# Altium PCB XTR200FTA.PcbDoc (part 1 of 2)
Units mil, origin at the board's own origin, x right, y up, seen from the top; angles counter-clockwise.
Board outline 3639.76 x 1623.7 mil, 4 copper layers (Top Layer, Layer 1, Layer 2, Bottom Layer), stack 53.912 mil thick; 93 components, 52 nets, 249 pads, 61 vias.
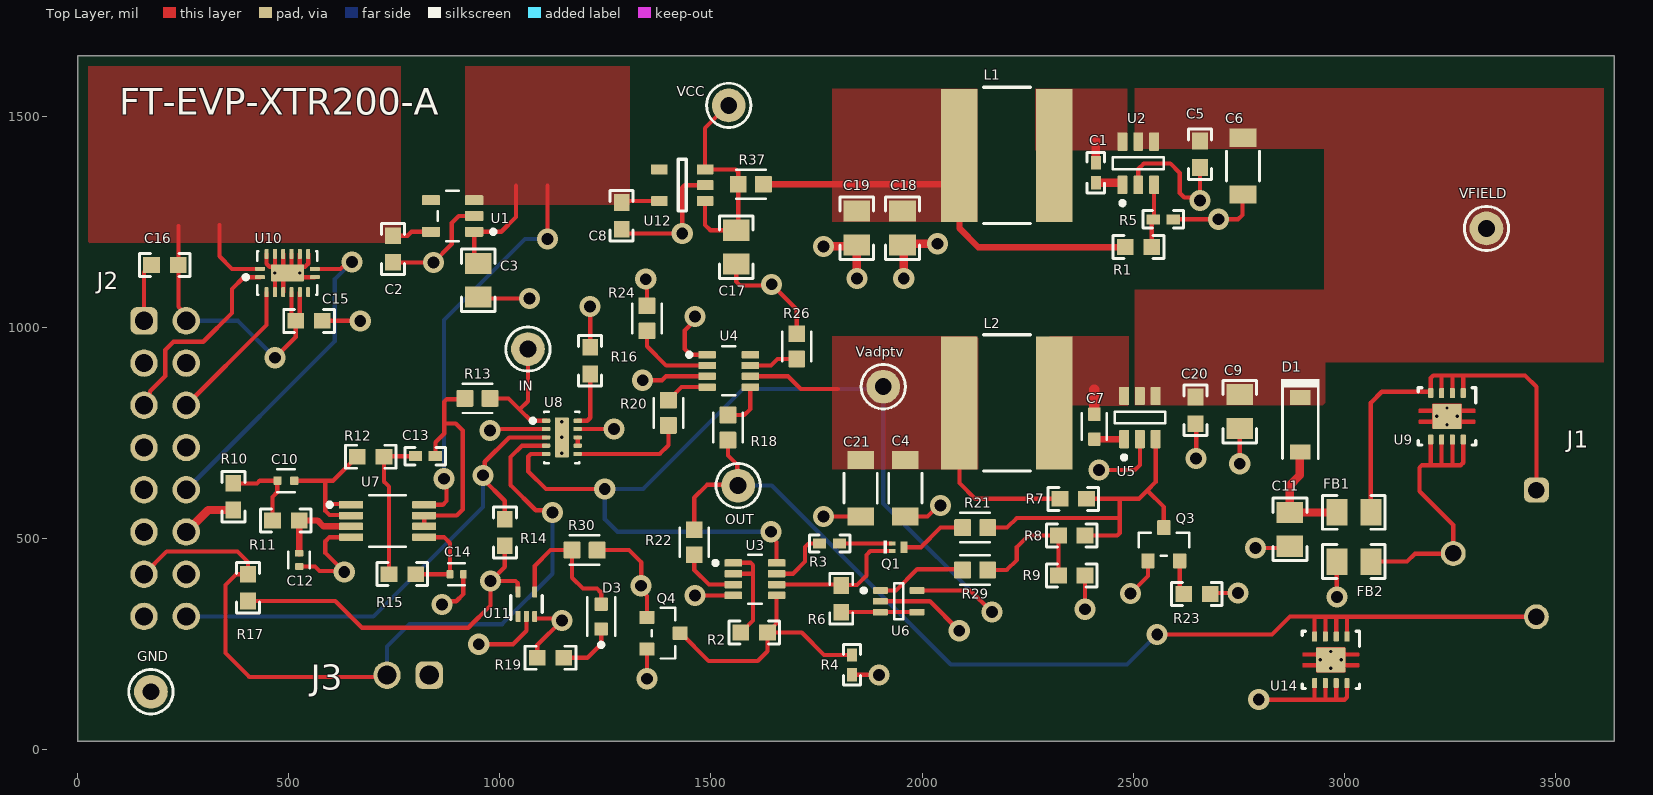
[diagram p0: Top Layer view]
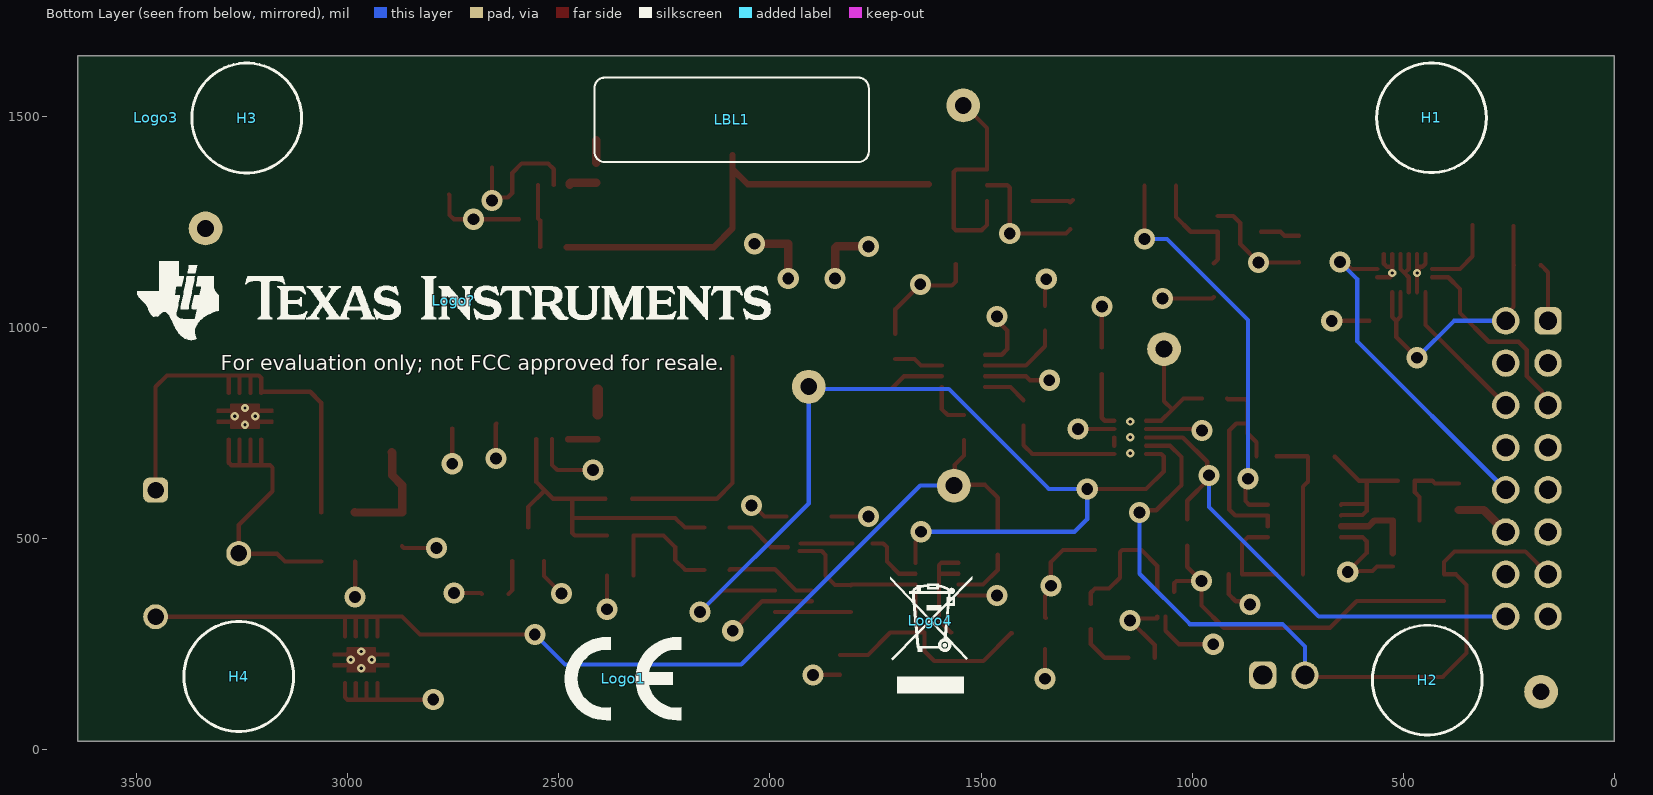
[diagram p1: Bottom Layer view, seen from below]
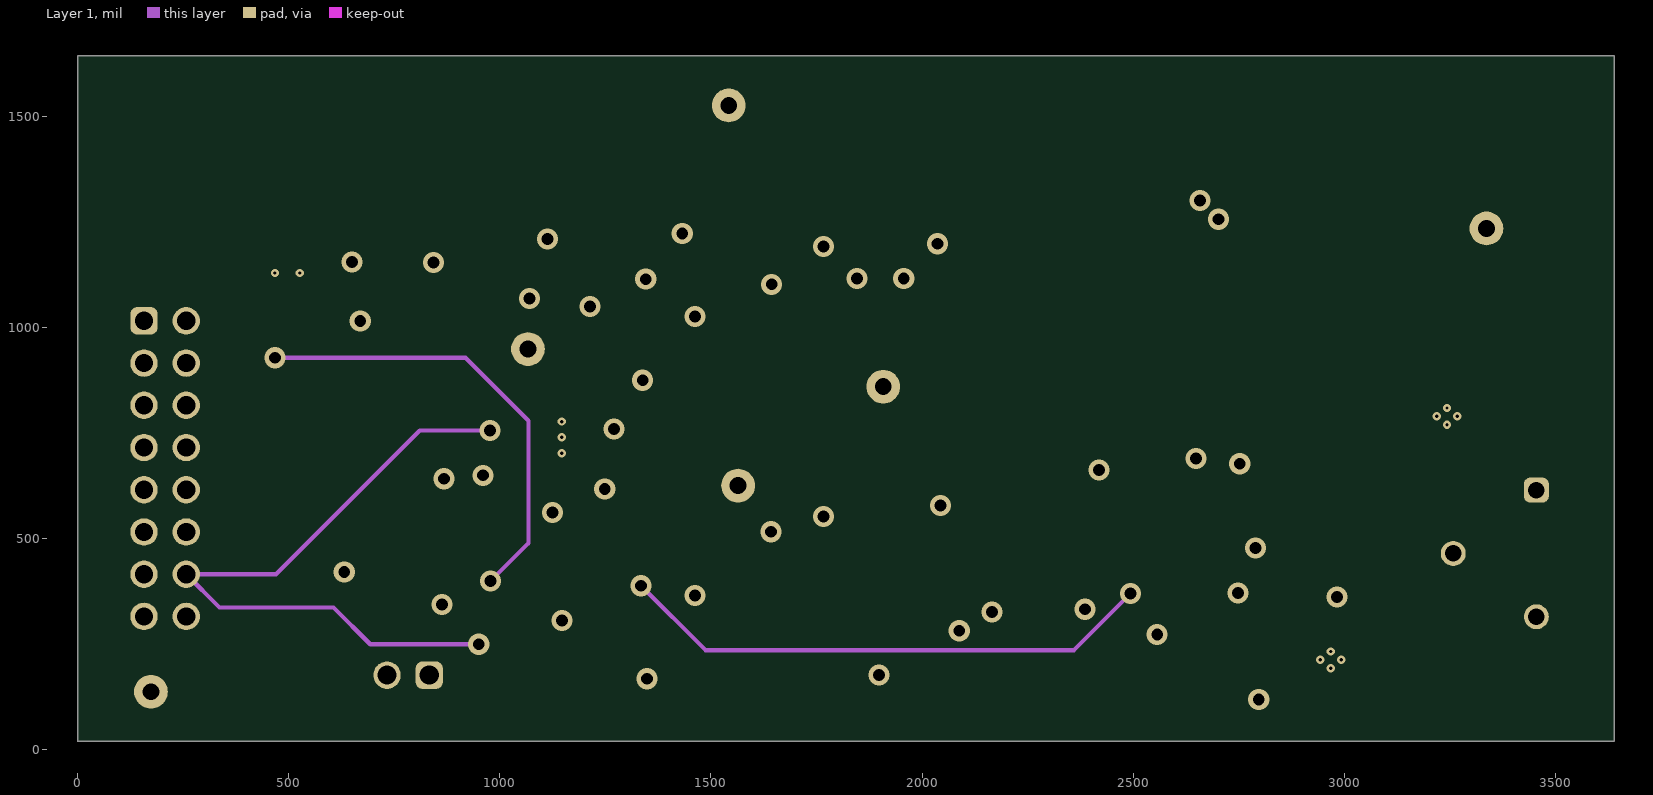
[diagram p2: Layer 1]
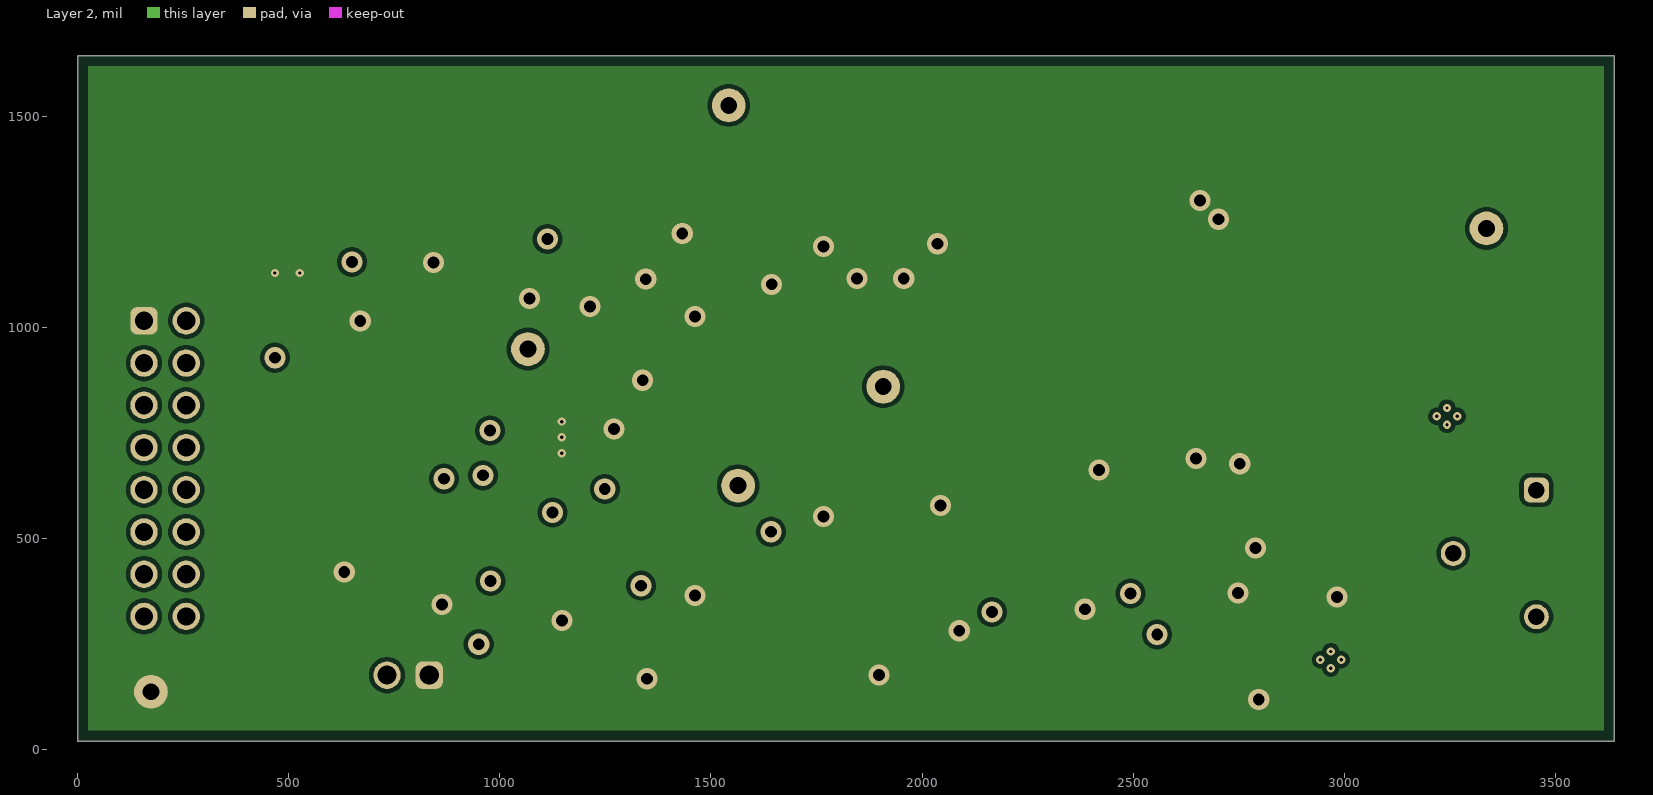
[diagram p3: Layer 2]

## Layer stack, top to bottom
Top Solder: solder mask 1, SM-001, Dk 4
Top Layer: signal copper 1.378
Dielectric 1: prepreg 5.1, PP-017, Dk 4.3
Dielectric 3: prepreg 5.1, PP-017, Dk 4.3
Layer 1: signal copper 1.378
Dielectric1: core 28, Core-039, Dk 4.8
Layer 2: signal copper 1.378
Dielectric 4: prepreg 5.1, PP-017, Dk 4.3
Dielectric 2: prepreg 5.1, PP-017, Dk 4.3
Bottom Layer: signal copper 1.378
Bottom Solder: solder mask 1, SM-001, Dk 4

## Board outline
-0.01,20 3639.75,20 3639.75,1643.7 -0.01,1643.7

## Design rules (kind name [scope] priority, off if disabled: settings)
AcuteAngle [All] p1: minimum=4.50000000000000E+0001 checktracksonly=FALSE
AssemblyTestPointUsage [All] p1: valid=2
BoardOutlineClearance BoardOutlineClearance_MountingHoles [OnCopper and InComponentClass('Mounting Holes')] p1: gap=39.37 ignorepadtopadclearanceinfootprint=FALSE
BoardOutlineClearance BoardOutlineClearance_Poly [OnCopper and IsPoly] p2: gap=25 ignorepadtopadclearanceinfootprint=FALSE
BoardOutlineClearance [OnCopper and Not InComponentClass('Logo') and not InComponentClass('FiducialMark') and not InRegion(1000,500,4000,800) and not InPoly] p3: gap=40 ignorepadtopadclearanceinfootprint=FALSE
Clearance Clearance_Keepouts [((IsTrack Or IsArc) And Not InPoly) And IsFree and IsKeepOut vs ((IsTrack Or IsArc) And Not InPoly) And IsFree and IsKeepOut] p1: gap=3.94 ignorepadtopadclearanceinfootprint=TRUE
Clearance Clearance_Poly [InPolygon] p2: gap=10 ignorepadtopadclearanceinfootprint=TRUE
Clearance Clearance_FiducialMark [IsKeepOut and InComponentClass('FiducialMark') vs IsPad and InComponentClass('FiducialMark')] p3: gap=0 ignorepadtopadclearanceinfootprint=FALSE
Clearance [All] p4: gap=3.94 ignorepadtopadclearanceinfootprint=TRUE
ComponentClearance ComponentClearance_MountingHoles_FiducialMarks [InComponentClass('Mounting Holes') vs InComponentClass('FiducialMark')] p1: gap=50 collisioncheckmode=3 verticalgap=10 showdistances=FALSE
ComponentClearance ComponentClearance_Shunt [InComponentClass('Header') vs InComponentClass('Shunt')] p2: gap=0 collisioncheckmode=3 verticalgap=0 showdistances=FALSE
ComponentClearance ComponentClearance_Logo [InComponentClass('Logo')] p3: gap=30 collisioncheckmode=3 verticalgap=10 showdistances=FALSE
ComponentClearance ComponentClearance_ScrewToNut [(HasFootprint('NY PMS 440 0025 PH')) vs (HasFootprint('Keystone_1902C'))] p4: gap=5 collisioncheckmode=3 verticalgap=10 showdistances=FALSE
ComponentClearance ComponentClearance_MountingHoles [InComponentClass('Mounting Holes')] p5: gap=100 collisioncheckmode=3 verticalgap=100000 showdistances=FALSE
ComponentClearance ComponentClearance_SmallPassives [HasFootprint('0201*') or HasFootprint('0402*') or HasFootprint('0508') or HasFootprint('0603*') or HasFootprint('0612') or HasFootprint('0805*') or HasFootprint('0815*') or HasFootprint('0830*') or HasFootprint('1206*') or HasFootprint('1210*') or HasFootprint('1808*') or HasFootprint('1812*') or HasFootprint('1825*') or HasFootprint('2010*') or HasFootprint('2220*') or HasFootprint('2225*') or HasFootprint('2512*') or HasFootprint('2728*') or HasFootprint('3518*') vs HasFootprint('0201*') or HasFootprint('0402*') or HasFootprint('0508') or HasFootprint('0603*') or HasFootprint('0612') or HasFootprint('0805*') or HasFootprint('0815*') or HasFootprint('0830*') or HasFootprint('1206*') or HasFootprint('1210*') or HasFootprint('1808*') or HasFootprint('1812*') or HasFootprint('1825*') or HasFootprint('2010*') or HasFootprint('2220*') or HasFootprint('2225*') or HasFootprint('2512*') or HasFootprint('2728*') or HasFootprint('3518*')] p6: gap=14.96 collisioncheckmode=3 verticalgap=10 showdistances=FALSE
ComponentClearance ComponentClearance_THtoSMT [IsThruComponent vs IsSMTComponent] p7: gap=30 collisioncheckmode=3 verticalgap=30 showdistances=FALSE
ComponentClearance ComponentClearance_THtoTH [IsThruComponent vs IsThruComponent] p8: gap=20 collisioncheckmode=3 verticalgap=30 showdistances=FALSE
ComponentClearance [All] p9: gap=20 collisioncheckmode=3 verticalgap=10 showdistances=FALSE
DiffPairsRouting [All] p1: maxlimit=100 minlimit=10 mostfreqgap=10 toplayer_minwidth=15 toplayer_maxwidth=15 toplayer_prefwidth=15 midlayer1_minwidth=15 midlayer1_maxwidth=15 midlayer1_prefwidth=15 midlayer2_minwidth=15 midlayer2_maxwidth=15 midlayer2_prefwidth=15 bottomlayer_minwidth=15 bottomlayer_maxwidth=15 bottomlayer_prefwidth=15 maxuncoupledlength=1000
FabricationTestPointUsage TestPointUsage [All] p1: valid=2 allowmultiple=FALSE
FabricationTestpoint Testpoint [All] p1: side=3 testpointundercomponent=TRUE minsize=40 maxsize=100 preferedsize=60 minholesize=0 maxholesize=40 preferedholesize=32 testpointgrid=1 allowsidetop=TRUE allowsidebottom=TRUE usegrid=TRUE gridtolerance=0.01
FanoutControl Fanout_LCC [IsLCC] p1: bgadir=Out bgaviamode=Centered fanoutstyle=Auto fanoutdirection=Alternating viagrid=1 // Fanout_LCC (Default Rule)
FanoutControl Fanout_BGA [IsBGA] p2: bgadir=Out bgaviamode=Centered fanoutstyle=Auto fanoutdirection=Alternating viagrid=1 // Fanout_BGA (Default Rule)
FanoutControl Fanout_Default [All] p4: bgadir=Out bgaviamode=Centered fanoutstyle=Auto fanoutdirection=Alternating viagrid=1 // Fanout_Default (Default Rule)
FanoutControl Fanout_Small [(CompPinCount < 5)] p5: bgadir=Out bgaviamode=Centered fanoutstyle=Auto fanoutdirection=OutThenIn viagrid=1 // Fanout_Small (Default Rule)
HoleSize [All] p1: absolutevalues=TRUE maxlimit=251 minlimit=7.87 maxpercent=80.000 minpercent=20.000
MinimumAnnularRing MinimumAnnularRing_ThermalPadVias [IsVia and InAnyComponent] p1: minimumring=5.91
MinimumAnnularRing [All] p2: minimumring=7.09
MinimumSolderMaskSliver MinimumSolderMaskSliver_Logo [InComponentClass('Logo') vs InComponentClass('Logo')] p1: minsoldermaskwidth=0.7
MinimumSolderMaskSliver [All] p2: minsoldermaskwidth=3.94
PlaneConnect [All] p1: planeconnectstyle=Relief reliefexpansion=10 reliefentries=4 reliefconductorwidth=10 reliefairgap=10
PolygonConnect [All] p1: connectstyle=Direct reliefconductorwidth=10 reliefentries=4 polygonreliefangle="90 Angle" airgapwidth=10
RoutingVias [All] p1: holewidth=16 width=34 viastyle="Through Hole" minholewidth=19.68 minwidth=33.86 maxholewidth=40 maxwidth=65
RoutingVias ThermalPadVias [IsVia and InAnyComponent] p2: holewidth=7.87 width=19.68 viastyle="Through Hole" minholewidth=7.87 minwidth=19.68 maxholewidth=12.99 maxwidth=23.62
SilkToBoardRegionClearance [Not ((IsComment or IsDesignator) And (Hide <> 'False')) and not InRegion(1000,500,4000,800)] p1:
SilkToSilkClearance SilkToSilkClearance_Pb-FreeLogo [(HasFootprint('Pb-Free_Overlay_Medium') OR HasFootprint('Pb-Free_Overlay_Small')) vs (HasFootprint('Pb-Free_Overlay_Medium') OR HasFootprint('Pb-Free_Overlay_Small'))] p1: silktosilkclearance=0
SilkToSilkClearance [All] p2: silktosilkclearance=3.94
SilkToSolderMaskClearance SilkToComponentPadClearance [(IsPad or IsFill or IsRegion) and InAnycomponent] p1: minsilkscreentomaskgap=5 clearancetoexposedcopper=TRUE
SilkToSolderMaskClearance "Silk to Solder Mask Opening" [All] p2: minsilkscreentomaskgap=3.94 clearancetoexposedcopper=FALSE
SolderMaskExpansion TentAllVias [IsVia] p1: expansion=1.97 istentingtop=TRUE
SolderMaskExpansion SolderMaskExpansion_1 [All] p2: expansion=4 istentingtop=FALSE
SupplyNets "Schematic Supply Nets_2" [InNet('LDO_IN')] p1: voltage=0.000
SupplyNets "Schematic Supply Nets_7" [InNet('VDD-5V')] p2: voltage=0.000
SupplyNets "Schematic Supply Nets_6" [InNet('GND')] p3: voltage=0.000
SupplyNets "Schematic Supply Nets_4" [InNet('VDD-3V3')] p4: voltage=0.000
SupplyNets "Schematic Supply Nets_1" [InNet('Vbuck_out')] p5: voltage=0.000
SupplyNets "Schematic Supply Nets" [InNet('Vfield')] p6: voltage=0.000
UnRoutedNet [All] p1: checkbadconnections=TRUE
Width [All] p1: maxlimit=100 minlimit=4 preferedwidth=10 checkconnectedcopper=TRUE
14 further rules are at their usual default settings.

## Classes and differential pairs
component class Schematic: C1 C2 C3 C4 C5 C6 C7 C8 C9 C10 C11 C12 C13 C14 C15 C16 C17 C18 C19 C20 C21 D1 D3 FB1 FB2 GND IN J1 J2 J3 L1 L2 OUT Q1 Q3 Q4 R1 R2 R3 R4 R5 R6 R7 R8 R9 R10 R11 R12 R13 R14 R15 R16 R17 R18 R19 R20 R21 R22 R23 R24 R26 R29 R30 R37 U1 U2 U3 U4 U5 U6 U7 U8 U9 U10 U11 U12 U14 Vadptv Vcc VFIELD
component class Header: J2 J3
component class Logo: Logo?
component class Hardware: H1 H2 H3 H4 LBL1 Logo1 Logo3 Logo4 Logo? ZZ1 ZZ2 ZZ3 ZZ4
component class AssemblyNote: ZZ1 ZZ2 ZZ3 ZZ4
component class Label: LBL1

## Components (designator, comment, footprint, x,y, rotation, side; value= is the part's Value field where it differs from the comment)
C1 "GRM155R71C104KA88D" 0402 2411.61,1366.14 r270 top value=0.1uF
C2 "885012206052" 0603 747.1,1185.48 r90 top value=1uF
C3 "GRM21BR71C225KA12L" 0805_HV 949.1,1111.48 r90 top value=2.2uF
C4 "C3216X6S1V106K160AC" 1206_180 1960.65,619.12 r90 top value=10uF
C5 "GRM188R72A104KA35D" 0603 2658.46,1409.88 r270 top value=0.1uF
C6 "GRM31CR71H475KA12L" 1206_180 2759.96,1381.68 r270 top value=4.7uF
C7 "KGF15AR71H104KT" FP-KGF15AR71H104KT_0603-MFG 2408.2,764.68 r90 top value=100nF
C8 "885012206052" 0603 1288.59,1263.99 r90 top value=1uF
C9 "GRM21BR61H475KE51L" 0805_HV 2752.33,800.53 r270 top value=4.7uF
C10 "CC0402KRX7R7BB123" FP-CC0402KRX7R7BB123_0402-MFG 493.37,636.81 r0 top value=12nF
C11 "CC0805KRX7R9BB102" 0805_HV 2871.06,521.49 r270 top value=1000pF
C12 "GRM155R71H103JA88D" FP-GRM155R71H103JA88D_0402-MFG 524.86,449.35 r90 top value=10nF
C13 "GRM155R71C683KA88D" 0402 823.83,694.88 r180 top value=0.068uF
C14 "GRM155R71H103JA88D" FP-GRM155R71H103JA88D_0402-MFG 897.94,415.35 r180 top value=10nF
C15 "885012206020" 0603 548.35,1015.35 r0 top value=0.1uF
C16 "885012206020" 0603 206.69,1147.25 r180 top value=0.1uF
C17 "GRM21BR71C225KA12L" 0805_HV 1559.78,1189.99 r90 top value=2.2uF
C18 "GRM21BR61A226ME44L" 0805_HV 1953.7,1235.08 r270 top value=22uF
C19 "GRM21BR61A226ME44L" 0805_HV 1845.44,1235.08 r270 top value=22uF
C20 "GRM188R72A104KA35D" 0603 2647.42,803.5 r270 top value=0.1uF
C21 "C3216X6S1V106K160AC" 1206_180 1854.52,619.12 r90 top value=10uF
D1 "SD103AW-7-F" SOD-123 2895.73,769.05 r270 top value=40V
D3 "LTST-C190KFKT" FP-LTST-C190KFKT_0603-MFG 1240.16,314.96 r90 top
FB1 "742792041" 0805_HV 3022.73,561.77 r0 top value="600 ohm"
FB2 "742792041" 0805_HV 3022.73,445.23 r0 top value="600 ohm"
GND "GND" Keystone5002 173.88,137.01 r0 top (schematic designator TP1)
H1 "SJ5382" 3M_SJ5382 433.39,1496.06 r180 bottom
H2 "SJ5382" 3M_SJ5382 443.29,164.64 r180 bottom
H3 "SJ5382" 3M_SJ5382 3239.15,1495.57 r180 bottom
H4 "SJ5382" 3M_SJ5382 3257.87,173.07 r180 bottom
IN "GND" Keystone5002 1066.69,948.43 r90 top (schematic designator TP4)
J1 "691412320003" Wurth_691412320003 3356.3,464.57 r90 top
J2 "61301621021" Wurth_61301621021 207.48,665.35 r0 top
J3 "61300211121" WURTH_61300211121 782.99,176.25 r180 top
L1 "SRN8040-220M" SRN8040 2200.76,1407.48 r0 top value=22uH
L2 "SRN8040-330M" SRN8040 2200.76,821.05 r0 top value=33uH
LBL1 "THT-14-423-10" Label_650x200 2090.83,1491.29 r180 bottom
Logo1 "CE Mark" CE_Mark_5mm 2347.73,167.91 r180 bottom
Logo3 "FCC disclaimer" FCC_disclaimer 3454.72,1496.06 r180 bottom
Logo4 "WEEE logo" WEEE_Minimum 1620.08,305.65 r180 bottom
Logo? "Texas Instruments" TI_Horizontal_Overlay_Medium 2748.23,1062.99 r180 bottom
OUT "GND" Keystone5002 1564.42,625.11 r90 top (schematic designator TP2)
Q1 "MMBT3904LP" DIODES_X1-DFN1006-3 1943.54,479.33 r0 top value="40 V"
Q3 "NTR4003NT3G" FP-NTR4003NT3G_SOT23-3-MFG 2572.57,486.31 r90 top
Q4 "NTR4003NT3G" FP-NTR4003NT3G_SOT23-3-MFG 1387.8,275.59 r0 top
R1 "CRCW0603169KFKEA" 0603 2512.59,1189.99 r180 top value=169k
R2 "CRCW0603261KFKEA" 0603 1602.36,277.11 r0 top value=261k
R3 "ERA-2AEB102X" 0402 1780.92,488.23 r0 top value=1.00k
R4 "RC0402FR-0715KL" 0402 1834.02,200.62 r90 top value=15.0k
R5 "CRCW040222K1FKED" 0402 2570.87,1255.88 r180 top value=22.1k
R6 "RC0603FR-074K87L" 0603 1808.71,357.08 r90 top value=4.87k
R7 "RC0603FR-0790K9L" 0603 2358.02,593.93 r180 top value=90.9k
R8 "RT0603BRD076K49L" 0603 2354.49,506.93 r0 top value=6.49k
R9 "RT0603BRD073K4L" 0603 2354.49,412.26 r180 top value=3.40k
R10 "RC0603FR-076K19L" 0603 369.01,598.96 r90 top value=6.19k
R11 "RT0603DRE078K87L" 0603 493.37,542.72 r0 top value=8.87k
R12 "RT0603DRE072K49L" 0603 694.32,693.49 r180 top value=2.49k
R13 "WSL060300000ZEA9" FP-WSL060300000ZEA9_0603-MFG 947.14,831.75 r180 top value=0
R14 "RG1608P-104-B-T5" 0603 1011.86,514.17 r270 top value=100k
R15 "RT0603DRE073K74L" 0603 769.21,415.35 r0 top value=3.74k
R16 "RT0603BRD071K37L" 0603 1213.99,920.95 r270 top value=1.37k
R17 "RG1608P-104-B-T5" 0603 403.5,383.55 r270 top value=100k
R18 "WSL060300000ZEA9" FP-WSL060300000ZEA9_0603-MFG 1540.17,762.62 r90 top value=0
R19 "RT0603DRE071KL" 0603 1120.08,217.52 r180 top value=1.00k
R20 "WSL060300000ZEA9" FP-WSL060300000ZEA9_0603-MFG 1399.27,797.54 r270 top value=0
R21 "WSL060300000ZEA9" FP-WSL060300000ZEA9_0603-MFG 2125.75,525.68 r0 top value=0
R22 "WSL060300000ZEA9" FP-WSL060300000ZEA9_0603-MFG 1460.63,491.03 r90 top value=0
R23 "RT0603BRD0711K8L" 0603 2650.81,368.66 r180 top value=11.8k
R24 "WSL060300000ZEA9" FP-WSL060300000ZEA9_0603-MFG 1348.43,1021.37 r270 top value=0
R26 "WSL060300000ZEA9" FP-WSL060300000ZEA9_0603-MFG 1703,954.86 r270 top value=0
R29 "WSL060300000ZEA9" FP-WSL060300000ZEA9_0603-MFG 2125.75,425.29 r0 top value=0
R30 "WSL060300000ZEA9" FP-WSL060300000ZEA9_0603-MFG 1200.79,472.44 r180 top value=0
R37 "WSL060300000ZEA9" FP-WSL060300000ZEA9_0603-MFG 1594.49,1338.58 r180 top value=0
U1 "TPS7A0333DBVR" DBV0005A-MFG 888.1,1263.63 r180 top
U2 "LMR54406DBVR" DBV0006A-MFG 2511.93,1388.54 r90 top
U3 "TLV9302IDDFR" DDF0008A-MFG 1604.33,403.54 r0 top
U4 "TPS26611DDFR" DDF0008A-MFG 1542.14,896.79 r0 top
U5 "LMR54406DBVR" DBV0006A-MFG 2515.78,786.41 r90 top
U6 "TLV9301IDCKR" DCK0005A-MFG 1944.45,351.18 r0 top
U7 "OPA2991IDGKR" DGK0008A-MFG 734.31,541.44 r0 top
U8 "XTR200IDQCR" DQC0010A-MFG 1147.07,739.37 r0 top
U9 "TVS3301DRBR" DRB0008A 3243.1,789.29 r270 top
U10 "SN74LV8T165BQBR" BQB0016A-MFG 497,1128.58 r90 top
U11 "SN74LVC1G04DRLR" DRL0005A 1062.99,344.49 r90 top
U12 "TPS70950DBVR" DBV0005A_N 1432.09,1336.61 r180 top
U14 "TVS3301DRBR" DRB0008A 2967.87,212.6 r270 top
Vadptv "GND" Keystone5002 1908.15,859.46 r90 top (schematic designator TP6)
VCC "GND" Keystone5002 1542.14,1525.59 r90 top (schematic designator TP5)
VFIELD "GND" Keystone5002 3336.61,1234.22 r90 top (schematic designator TP3)
ZZ1 "This Assembly Note is for PCB labels only" AssemblyNoteLabel 185,3938 r0 top
ZZ2 "These assemblies are ESD sensitive, ESD precautions shall be observed." AssemblyNote 185,3829.11 r0 top
ZZ3 "These assemblies must be clean and free from flux and all contaminants. Use of no clean flux is not acceptable." AssemblyNote 185,3740.56 r0 top
ZZ4 "These assemblies must comply with workmanship standards IPC-A-610 Class 2, unless otherwise specified." AssemblyNote 185,3652 r0 top

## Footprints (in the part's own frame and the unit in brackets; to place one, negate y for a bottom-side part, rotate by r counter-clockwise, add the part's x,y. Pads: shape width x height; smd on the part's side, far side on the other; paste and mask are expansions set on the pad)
3M_SJ5382 [mil] "3M BUMPON"
  silkscreen extent -130,-130 130,130, body extent -125,-125 125,125, height 75
0402 [mm] "0402 from SM-752 data"
  rect 0.8x0.6 smd: 1(-0.6,0) 2(0.6,0)
  silkscreen extent -1.22,-0.52 1.22,0.52, body extent -0.55,-0.3 0.55,0.3, height 0.6
0603 [mm] "0603 from SM-752 data"
  rect 1x0.95 smd: 1(-0.8,0) 2(0.8,0)
  silkscreen extent -1.52,-0.69 1.52,0.69, body extent -0.87,-0.47 0.87,0.47, height 1
0805_HV [mil] "0805 with 30mil clearance between pads"
  rect 50x63 smd: 1(-40,0) 2(40,0)
  silkscreen extent -74,-40 74,40, body extent -43,-29 43,29, height 57
1206_180 [mm] "1206_180"
  rect 1.1x1.6 smd: 1(-1.7,0) 2(1.7,0)
  silkscreen extent -0.9,-1 0.9,1, body extent -1.75,-0.95 1.75,0.95, height 1.8
AssemblyNote [mil] "Assembly Note"
AssemblyNoteLabel [mil] "Assembly Note for PCB Labels"
BQB0016A-MFG [mm]
  rrect42% 0.24x0.6 smd paste+0 mask+0: 1(-0.25,1.65) 8(-0.25,-1.65) 9(0.25,-1.65) 16(0.25,1.65)
  rrect42% 0.6x0.24 smd paste+0 mask+0: 2(-1.15,1.25) 3(-1.15,0.75) 4(-1.15,0.25) 5(-1.15,-0.25) 6(-1.15,-0.75) 7(-1.15,-1.25) 10(1.15,-1.25) 11(1.15,-0.75) 12(1.15,-0.25) 13(1.15,0.25) 14(1.15,0.75) 15(1.15,1.25)
  rrect10% 1x2 smd paste-1000 mask+0: 17(0,0)
  silkscreen extent -1.3,-1.8 1.3,2.62, body extent -1.55,-2.05 1.55,2.05, height 0.25
CE_Mark_5mm [mil] "Minimum text height for CE Mark"
  silkscreen extent -138,-98 138,98
DBV0005A-MFG [mm]
  rrect17% 1.1x0.6 smd paste+0 mask+0: 1(-1.3,0.95) 2(-1.3,0) 3(-1.3,-0.95) 4(1.3,-0.95) 5(1.3,0.95)
  silkscreen extent -2.58,-1.53 0.87,1.53, body extent -1.95,-1.78 1.95,1.78, height 0.25
DBV0005A_N [mm] "SOT23, 5-Leads, Body 2.9x1.6mm, Pitch 0.95mm, Lead Span 2.8mm, IPC Medium Density"
  rrect17% 1x0.6 smd: 1(-1.375,0.95) 2(-1.375,0) 3(-1.375,-0.95) 4(1.375,-0.95) 5(1.375,0.95)
  silkscreen extent -0.25,-1.55 0.25,1.55, body extent -1.42,-1.46 1.42,1.46, height 1.09
DBV0006A-MFG [mm]
  rrect17% 1.1x0.6 smd paste+0 mask+0: 1(-1.3,0.95) 2(-1.3,0) 3(-1.3,-0.95) 4(1.3,-0.95) 5(1.3,0) 6(1.3,0.95)
  silkscreen extent -2.52,-1.53 0.35,1.53, body extent -1.95,-1.78 1.95,1.78, height 0.25
DCK0005A-MFG [mm]
  rrect25% 0.9x0.4 smd paste-1000 mask+0: 1(-1.1,0.65) 2(-1.1,0) 3(-1.1,-0.65) 4(1.1,-0.65) 5(1.1,0.65)
  silkscreen extent -2.22,-1.07 0.27,1.07, body extent -1.65,-1.33 1.65,1.33, height 0.25
DDF0008A-MFG [mm] "Recommended Land Pattern"
  rrect22% 1.05x0.45 smd paste+0 mask+0: 1(-1.3,0.975) 2(-1.3,0.325) 3(-1.3,-0.325) 4(-1.3,-0.975) 5(1.3,-0.975) 6(1.3,-0.325) 7(1.3,0.325) 8(1.3,0.975)
  silkscreen extent -2.5,-1.48 0.4,1.48, body extent -1.41,-1.45 1.41,1.45, height 1.1
DGK0008A-MFG [mm]
  rrect22% 1.45x0.45 smd paste+0 mask+0: 1(-2.2,0.975) 2(-2.2,0.325) 3(-2.2,-0.325) 4(-2.2,-0.975) 5(2.2,-0.975) 6(2.2,-0.325) 7(2.2,0.325) 8(2.2,0.975)
  silkscreen extent -3.61,-1.55 1.1,1.55, body extent -3.03,-1.8 3.03,1.8, height 0.25
DIODES_X1-DFN1006-3 [mm] "Diodes Recommended"
  rect 0.4x0.25 smd: 1(-0.35,0.225) 2(-0.35,-0.225)
  rect 0.4x0.7 smd: 3(0.35,0)
  silkscreen extent -0.87,-0.38 -0.69,0.38, body extent -0.54,-0.34 0.54,0.34, height 0.53
DQC0010A-MFG [mm] "Recommended Land Pattern"
  rrect40% 0.5x0.25 smd paste+0 mask+0: 1(-0.95,1) 2(-0.95,0.5) 3(-0.95,0) 4(-0.95,-0.5) 5(-0.95,-1) 6(0.95,-1) 7(0.95,-0.5) 8(0.95,0) 9(0.95,0.5) 10(0.95,1)
  rrect12% 0.84x2.4 smd paste-1000 mask+0: 11(0,0)
  silkscreen extent -1.87,-1.55 1.05,1.55, body extent -1.3,-1.65 1.3,1.65, height 0.25
DRB0008A [mm] "VSON-8"
  rrect32% 0.6x0.31 smd: 1(-1.4,0.975) 2(-1.4,0.325) 3(-1.4,-0.325) 4(-1.4,-0.975) 5(1.4,-0.975) 6(1.4,-0.325) 7(1.4,0.325) 8(1.4,0.975)
  rrect7% 1.5x1.75 smd paste-0.75: 9(0,0)
  Top Layer region: -0.7,-0.875 -0.49,-0.875 -0.471,-0.879 -0.455,-0.89 -0.444,-0.906 -0.44,-0.925 -0.44,-0.925 -0.44,-1.65 -0.436,-1.669 -0.425,-1.685 -0.409,-1.696 -0.39,-1.7 -0.39,-1.7 -0.26,-1.7 -0.241,-1.696 -0.225,-1.685 -0.214,-1.669 -0.21,-1.65 -0.21,-1.65 -0.21,-0.925 -0.206,-0.906 -0.195,-0.89 -0.179,-0.879 -0.16,-0.875 -0.16,-0.875 0.16,-0.875 0.179,-0.879 0.195,-0.89 0.206,-0.906 0.21,-0.925 0.21,-0.925 0.21,-1.65 0.21,-1.65 0.214,-1.669 0.225,-1.685 0.241,-1.696 0.26,-1.7 0.26,-1.7 0.39,-1.7 0.409,-1.696 0.425,-1.685 0.436,-1.669 0.44,-1.65 0.44,-1.65 0.44,-0.925 0.444,-0.906 0.455,-0.89 0.471,-0.879 0.49,-0.875 0.49,-0.875 0.7,-0.875 0.719,-0.871 0.735,-0.86 0.746,-0.844 0.75,-0.825 0.75,-0.825 0.75,0.825 0.746,0.844 0.735,0.86 0.719,0.871 0.7,0.875 0.7,0.875 0.49,0.875 0.471,0.879 0.455,0.89 0.444,0.906 0.44,0.925 0.44,0.925 0.44,1.65 0.436,1.669 0.425,1.685 0.409,1.696 0.39,1.7 0.39,1.7 0.26,1.7 0.241,1.696 0.225,1.685 0.214,1.669 0.21,1.65 0.21,1.65 0.21,1.65 0.21,0.925 0.206,0.906 0.195,0.89 0.179,0.879 0.16,0.875 0.16,0.875 -0.16,0.875 -0.179,0.879 -0.195,0.89 -0.206,0.906 -0.21,0.925 -0.21,0.925 -0.21,1.65 -0.214,1.669 -0.225,1.685 -0.241,1.696 -0.26,1.7 -0.26,1.7 -0.39,1.7 -0.409,1.696 -0.425,1.685 -0.436,1.669 -0.44,1.65 -0.44,1.65 -0.44,0.925 -0.444,0.906 -0.455,0.89 -0.471,0.879 -0.49,0.875 -0.49,0.875 -0.7,0.875 -0.719,0.871 -0.735,0.86 -0.746,0.844 -0.75,0.825 -0.75,0.825 -0.75,-0.825 -0.746,-0.844 -0.735,-0.86 -0.719,-0.871 -0.7,-0.875
  silkscreen extent -1.73,-1.73 1.73,1.73, body extent -1.5,-1.5 1.5,1.5, height 0.77
DRL0005A [mm] "SOTFL, 5-Flat Leads, Body 1.2x1.6x0.6mm, Pitch 0.5mm, TI recommended"
  rrect33% 0.67x0.3 smd: 1(-0.74,0.5) 2(-0.74,0) 3(-0.74,-0.5) 4(0.74,-0.5) 5(0.74,0.5)
  silkscreen extent -0.9,-0.95 0.5,0.95, body extent -0.85,-0.85 0.85,0.85, height 0.62
FCC_disclaimer [mil]
FP-CC0402KRX7R7BB123_0402-MFG [mm]
  rrect20% 0.5x0.5 smd paste+0 mask+0: 1(-0.5,0) 2(0.5,0)
  silkscreen extent -0.53,-0.7 0.53,0.7, body extent -0.87,-0.48 0.87,0.48, height 0.25
FP-GRM155R71H103JA88D_0402-MFG [mm]
  rrect25% 0.4x0.5 smd paste+0 mask+0: 1(-0.4,0) 2(0.4,0)
  silkscreen extent -0.5,-0.65 0.5,0.65, body extent -0.7,-0.38 0.7,0.38, height 0.25
FP-KGF15AR71H104KT_0603-MFG [mm]
  rrect13% 0.8x0.75 smd paste+0 mask+0: 1(-0.75,0) 2(0.75,0)
  silkscreen extent -0.8,-0.75 0.8,0.75, body extent -1.25,-0.58 1.25,0.58, height 0.25
FP-LTST-C190KFKT_0603-MFG [mm]
  rrect13% 0.8x0.8 smd paste+0 mask+0: 1(-0.75,0) 2(0.75,0)
  silkscreen extent -1.82,-0.85 1.15,0.85, body extent -1.25,-0.55 1.25,0.55, height 0.25
FP-NTR4003NT3G_SOT23-3-MFG [mm] "Recommended Land Pattern"
  rrect13% 0.9x0.8 smd paste+0 mask+0: 1(-1,0.95) 2(-1,-0.95) 3(1,0)
  silkscreen extent -0.7,-1.52 0.7,1.52, body extent -1.2,-1.45 1.2,1.45, height 1.11
FP-WSL060300000ZEA9_0603-MFG [mm]
  rrect10% 1.01x1.01 smd paste+0 mask+0: 1(-0.755,0) 2(0.755,0)
  silkscreen extent -0.89,-0.88 0.89,0.88, body extent -1.36,-0.61 1.36,0.61, height 0.25
Keystone5002 [mil] "For Keystone 500x miniature loop terminals"
  round 80 hole 40: 1(0,0)
  silkscreen extent -52,-52 52,52, body extent -49,-49 49,49, height 182
Label_650x200 [mil] "Thermal Transfer Label"
  round 1 on Mech14: 0(0,0)
  silkscreen extent -325,-100 325,100, body extent -325,-100 325,100, height 1
SOD-123 [mm] "On Semi recommended land pattern"
  rect 0.915x1.22 smd: 1(-1.637,0) 2(1.637,0)
  silkscreen extent -2.74,-1.17 2.03,1.17, body extent -1.93,-0.9 1.93,0.9, height 1.35
SRN8040 [mm] "SMD, 2-Leads, Body 8x8mm"
  rect 2.2x8 smd: 1(-2.85,0) 2(2.85,0)
  silkscreen extent -1.4,-4.1 1.4,4.1, body extent -4,-4 4,4, height 4
TI_Horizontal_Overlay_Medium [mil]
  silkscreen extent -750,-93 750,94
WEEE_Minimum [mil] "WEEElie bin"
  silkscreen extent -95,-172 99,104
WURTH_61300211121 [mm] "Header, 2.54mm, 2x1, TH"
  rrect50% 1.65x1.65 hole 1.15: 1(-1.27,0)
  round 1.65 hole 1.15: 2(1.27,0)
  body extent -2.54,-1.27 2.54,1.27, height 8.54
Wurth_61301621021 [mm] "Header, 2.54mm, 8x2, R/A, TH"
  rrect50% 1.65x1.65 hole 1.1: 1(-1.27,8.89)
  round 1.65 hole 1.1: 2(1.27,8.89) 3(-1.27,6.35) 4(1.27,6.35) 5(-1.27,3.81) 6(1.27,3.81) 7(-1.27,1.27) 8(1.27,1.27) 9(-1.27,-1.27) 10(1.27,-1.27) 11(-1.27,-3.81) 12(1.27,-3.81) 13(-1.27,-6.35) 14(1.27,-6.35) 15(-1.27,-8.89) 16(1.27,-8.89)
  body extent -11.31,-10.16 1.59,10.16, height 5.08
Wurth_691412320003 [mm] "Terminal Block, 3 Position, 3.81mm, R/A, TH"
  rrect50% 1.5x1.5 hole 1: 1(3.81,-2.5)
  round 1.5 hole 1: 2(0,2.5) 3(-3.81,-2.5)
  body extent -7.06,-7.2 5.87,4.8, height 13.03

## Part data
C1: library part CMP-0006641-2, "CAP, CERM, 0.1 uF, 16 V, +/- 10%, X7R, 0402", Cap_Case=0402, Manufacturer=MuRata, Supplier Part Number 1=490-3261-1-ND, TempCo=X7R, Tolerance_%=10%, Value1=Unknown, Value2=16V, ValueDisplayed=0.1uF
C2 C8: library part CMP-0006831-4, "CAP, CERM, 1 uF, 16 V, +/- 10%, X7R, 0603", Cap_Case=0603, Manufacturer="Wurth Elektronik", Supplier Part Number 1=710-885012206052, TempCo=X7R, Tolerance_%=10%, Value1=Unknown, Value2=16V, ValueDisplayed=1uF
C3 C17: library part CMP-0008329-2, "CAP, CERM, 2.2 uF, 16 V, +/- 10%, X7R, 0805", Cap_Case=0805, Manufacturer=MuRata, Supplier Part Number 1=490-3906-1-ND, TempCo=X7R, Tolerance_%=10%, Value1="0.004 ohm", Value2=16V, ValueDisplayed=2.2uF
C4 C21: library part CMP-0008684-3, "CAP, CERM, 10 uF, 35 V, +/- 10%, X6S, 1206", Cap_Case=1206_180, Manufacturer=TDK, Supplier Part Number 1=445-14778-1-ND, TempCo=X6S, Tolerance_%=10%, Value1="0.002229 ohm", Value2=35V, ValueDisplayed=10uF
C5 C20: library part CMP-0007469-4, "CAP, CERM, 0.1 uF, 100 V, +/- 10%, X7R, 0603", Cap_Case=0603, Manufacturer=MuRata, Supplier Part Number 1=490-3285-1-ND, TempCo=X7R, Tolerance_%=10%, Value1=Unknown, Value2=100V, ValueDisplayed=0.1uF
C6: library part CMP-0008969-2, "CAP, CERM, 4.7 uF, 50 V, +/- 10%, X7R, 1206", Cap_Case=2220, Manufacturer=MuRata, Supplier Part Number 1=24R6347, TempCo=X7R, Tolerance_%=10%, Value1=Unknown, Value2=50V, ValueDisplayed=4.7uF
C7: library part CMP-0121004-1, "0.1 µF ±10% 50V Ceramic Capacitor X7R 0603 (1608 Metric)", Digikey Part Number=478-KGF15AR71H104KTCT-ND, Manufacturer="KYOCERA AVX", Operating Temperature Range="-55°C to +125°C", TempCo=15%, Temperature Characteristic=X7R, Tolerance_%=10%, ValueDisplayed=100nF
C9: library part CMP-0008309-2, "CAP, CERM, 4.7 uF, 50 V, +/- 10%, X5R, 0805", Cap_Case=0805, Manufacturer=MuRata, Supplier Part Number 1=GRM21BR61H475KE51L-ND, TempCo=X5R, Tolerance_%=10%, Value1=Unknown, Value2=50V, ValueDisplayed=4.7uF
C10: library part CMP-0109222-1, "0.012 µF ±10% 16V Ceramic Capacitor X7R 0402 (1005 Metric)", Digikey Part Number=311-3800-1-ND, Manufacturer=Yageo, Mouser Part Number=603-CC402KRX7R7BB123, Operating Temperature Range="-55°C to +125°C", TempCo=15%, Temperature Characteristic=X7R, Tolerance_%=10%, ValueDisplayed=12nF
C11: library part CMP-0007936-2, "CAP, CERM, 1000 pF, 50 V, +/- 10%, X7R, 0805", Cap_Case=0805, Manufacturer="Yageo America", Supplier Part Number 1=311-1127-1-ND, TempCo=X7R, Tolerance_%=10%, Value1=Unknown, Value2=50V, ValueDisplayed=1000pF
C12 C14: library part CMP-0096544-1, "Chip Multilayer Ceramic Capacitors for General Purpose, 0402, 10000pF, X7R, 15%, 5%, 50V", Manufacturer=Murata, Operating Temperature Range="-55°C to +125°C", TempCo=15%, Temperature Characteristic=X7R, Tolerance_%=5%, ValueDisplayed=10000pF
C13: library part CMP-0006655-2, "CAP, CERM, 0.068 uF, 16 V, +/- 10%, X7R, 0402", Cap_Case=0402, Manufacturer=MuRata, Supplier Part Number 1=490-3259-1-ND, TempCo=X7R, Tolerance_%=10%, Value1=Unknown, Value2=16V, ValueDisplayed=0.068uF
C15 C16: library part CMP-0064931-4, "CAP, CERM, 0.1 uF, 10 V,+/- 10%, X7R, 0603", Cap_Case=0603, Manufacturer="Wurth Elektronik", Supplier Part Number 1=732-7939-1-ND, TempCo=X7R, Tolerance_%=10%, Value1=Unknown, Value2=10V, ValueDisplayed=0.1uF
C18 C19: library part CMP-0008286-2, "CAP, CERM, 22 uF, 10 V, +/- 20%, X5R, 0805", Cap_Case=0805, Manufacturer=MuRata, Supplier Part Number 1=490-10746-1-ND, TempCo=X5R, Tolerance_%=20%, Value1=Unknown, Value2=10V, ValueDisplayed=22uF
D1: library part CMP-0028543-2, "Diode, Schottky, 40 V, 0.35 A, SOD-123", Manufacturer="Diodes Inc.", Value1=0.35A, Value2=0.55V
D3: library part CMP-0097262-1, "Orange 605nm LED Indication - Discrete 2V 0603 (1608 Metric)", Color=Orange, Digikey Part Number=160-1434-1-ND, Forward Current=20mA, Manufacturer=Lite-On, Mouser Part Number=859-LTST-C190KFKT, Operating Temperature Range="-35°C to +85°C", Power_TotalModule=75mW
FB1 FB2: library part CMP-0003085-1, "Ferrite Bead, 600 ohm @ 100 MHz, 0.2 A, 0805", Manufacturer="Wurth Elektronik", Supplier Part Number 1=732-1604-1-ND, Value1="0.4 ohm", Value2=0.2A, ValueDisplayed="600 ohm"
GND IN OUT Vadptv VCC VFIELD: library part CMP-0055139-2, "Test Point, Miniature, White, TH", Color=White, Manufacturer="Keystone Electronics", PartNumber=5002, Supplier Part Number 1=36-5002-ND
H1 H2 H3 H4: library part CMP-0003668-1, "Bumpon, Hemisphere, 0.25 X 0.075, Clear", Manufacturer=3M, Supplier Part Number 1=SJ5382-ND
J1: library part CMP-0083843-1, "Terminal Block, 3 Position, 3.81mm, Tin, R/A, TH", Color=Gray, Current_A=4A, Manufacturer="Wurth Elektronik", Voltage_V=300V
J2: library part CMP-0081505-1, "Header, 2.54mm, 8x2, Gold, R/A, TH", Color=Black, Current_A=3A, Manufacturer="Wurth Elektronik", Supplier Part Number 1=732-5356-ND, Voltage_V=250V
J3: library part CMP-0054794-2, "Header, 2.54 mm, 2x1, Gold, TH", Color=Black, Manufacturer="Wurth Elektronik", Supplier Part Number 1=732-5315-ND
L1: library part CMP-0057669-2, "Inductor, Drum Core, Ferrite, 22 uH, 2.2 A, 0.1 ohm, SMD", Manufacturer=Bourns, Supplier Part Number 1=SRN8040-220MCT-ND, Value1="0.1 ohm", Value2=2.2A, ValueDisplayed=22uH
L2: library part CMP-0057670-2, "Inductor, Drum Core, Ferrite, 33 uH, 1.7 A, 0.145 ohm, SMD", Manufacturer=Bourns, Supplier Part Number 1=SRN8040-330MCT-ND, Value1="0.145 ohm", Value2=1.7A, ValueDisplayed=33uH
LBL1: library part CMP-0003625-1, "Thermal Transfer Printable Labels, 0.650\" W x 0.200\" H - 10,000 per roll", Manufacturer=Brady, Supplier Part Number 1=97C5133
Logo1: library part CMP-0074844-1
Logo3: library part CMP-0074847-1, "FCC_disclaimer"
Logo4: library part CMP-0074769-1
Logo?: library part CMP-0074838-1, "Texas Instrument Corporate Signature"
Q1: library part CMP-0000409-2, "Transistor, NPN, 40 V, 0.2 A, 3-UFDFN", Manufacturer="Diodes Inc.", Supplier Part Number 1=MMBT3904LP-7BDICT-ND, Value1="0.2 A", Value2=400
Q3 Q4: library part CMP-0125365-1, "N-Channel 30V 500mA (Ta) 690mW (Ta) Surface Mount SOT-23-3 (TO-236)", Digikey Part Number=NTR4003NT3GOSCT-ND, Drain To Source Breakdown Voltage=30V, Input Capacitace At Vds="21pF @ 5V", Manufacturer="On Semiconductor", Mouser Part Number=863-NTR4003NT3G, Operating Temperature Range="-55°C to +150°C", Power_W=0.69W, Pulse Drain Current=1.7A, Typ Forward Diode Voltage=0.65V
R1: library part CMP-0022077-4, "RES, 169 k, 1%, 0.1 W, AEC-Q200 Grade 0, 0603", Manufacturer=Vishay-Dale, Power_W=100mW, Supplier Part Number 1=541-169KHCT-ND, TempCo="100 ppm/C", Tolerance_%=1%, Value2=0.1W, Value_Code=169k
R2: library part CMP-0022244-4, "RES, 261 k, 1%, 0.1 W, AEC-Q200 Grade 0, 0603", Manufacturer=Vishay-Dale, Power_W=100mW, Supplier Part Number 1=541-261KHCT-ND, TempCo="100 ppm/C", Tolerance_%=1%, Value2=0.1W, Value_Code=261k
R3: library part CMP-0026770-1, "RES, 1.00 k, 0.1%, 0.063 W, 0402", Manufacturer=Panasonic, Power_W=63mW, Supplier Part Number 1=P1.0KDCCT-ND, TempCo="25 ppm/C", Tolerance_%=0.1%, Value2=0.063W, Value_Code=1k00, ValueDisplayed=1.00k
R4: library part CMP-0078583-1, "RES, 15.0 k, 1%, 0.063 W, 0402", Manufacturer="Yageo America", Power_W=63mW, Supplier Part Number 1=311-15.0KLRCT-ND, TempCo="100 ppm/C", Tolerance_%=1%, Value2=0.063W, Value_Code=15k0, ValueDisplayed=15.0k
R5: library part CMP-0026178-2, "RES, 22.1 k, 1%, 0.063 W, AEC-Q200 Grade 0, 0402", Manufacturer=Vishay-Dale, Power_W=63mW, Supplier Part Number 1=541-22.1KLCT-ND, TempCo="100 ppm/C", Tolerance_%=1%, Value2=0.063W, Value_Code=22k1, ValueDisplayed=22.1k
R6: library part CMP-0023154-5, "RES, 4.87 k, 1%, 0.1 W, 0603", Manufacturer=Yageo, Power_W=100mW, Supplier Part Number 1=311-4.87KHRCT-ND, TempCo="100 ppm/C", Tolerance_%=1%, Value2=0.1W, Value_Code=4k87, ValueDisplayed=4.87k
R7: library part CMP-0023314-5, "RES, 90.9 k, 1%, 0.1 W, 0603", Manufacturer=Yageo, Power_W=100mW, Supplier Part Number 1=311-90.9KHRCT-ND, TempCo="100 ppm/C", Tolerance_%=1%, Value2=0.1W, Value_Code=90k9, ValueDisplayed=90.9k
R8: library part CMP-0024436-2, "RES, 6.49 k, 0.1%, 0.1 W, 0603", Manufacturer="Yageo America", Power_W=100mW, TempCo="25 ppm/C", Tolerance_%=0.1%, Value2=0.1W, Value_Code=6k49, ValueDisplayed=6.49k
R9: library part CMP-0024198-2, "RES, 3.40 k, 0.1%, 0.1 W, 0603", Manufacturer="Yageo America", Power_W=100mW, TempCo="25 ppm/C", Tolerance_%=0.1%, Value2=0.1W, Value_Code=3k40, ValueDisplayed=3.40k
R10: library part CMP-0023247-5, "RES, 6.19 k, 1%, 0.1 W, 0603", Manufacturer=Yageo, Power_W=100mW, Supplier Part Number 1=311-6.19KHRCT-ND, TempCo="100 ppm/C", Tolerance_%=1%, Value2=0.1W, Value_Code=6k19, ValueDisplayed=6.19k
R11: library part CMP-0025632-3, "RES, 8.87 k, 0.5%, 0.1 W, 0603", Manufacturer="Yageo America", Power_W=100mW, TempCo="50 ppm/C", Tolerance_%=0.5%, Value2=0.1W, Value_Code=8k87, ValueDisplayed=8.87k
R12: library part CMP-0025063-3, "RES, 2.49 k, 0.5%, 0.1 W, 0603", Manufacturer="Yageo America", Power_W=100mW, TempCo="50 ppm/C", Tolerance_%=0.5%, Value2=0.1W, Value_Code=2k49, ValueDisplayed=2.49k
R13 R18 R20 R21 R22 R24 R26 R29 R30 R37: library part CMP-0031931-1, "0 Ohms Jumper Chip Resistor 0603 (1608 Metric) Metal Element", Digikey Part Number=541-3927-1-ND, Manufacturer=Vishay, Mouser Part Number=71-WSL060300000ZEA9, Operating Temperature Range="-65°C to +170°C", TempCo=3900ppm/°C
R14 R17: library part CMP-0023405-3, "RES, 100 k, 0.1%, 0.1 W, 0603", Manufacturer="Susumu Co Ltd", Power_W=100mW, Supplier Part Number 1=RG16P100KBCT-ND, TempCo="25 ppm/C", Tolerance_%=0.1%, Value2=0.1W, Value_Code=100k
R15: library part CMP-0025228-3, "RES, 3.74 k, 0.5%, 0.1 W, 0603", Manufacturer="Yageo America", Power_W=100mW, TempCo="50 ppm/C", Tolerance_%=0.5%, Value2=0.1W, Value_Code=3k74, ValueDisplayed=3.74k
R16: library part CMP-0023886-3, "RES, 1.37 k, 0.1%, 0.1 W, 0603", Manufacturer="Yageo America", Power_W=100mW, TempCo="25 ppm/C", Tolerance_%=0.1%, Value2=0.1W, Value_Code=1k37, ValueDisplayed=1.37k
R19: library part CMP-0024852-2, "RES, 1.00 k, 0.5%, 0.1 W, 0603", Manufacturer="Yageo America", Power_W=100mW, TempCo="50 ppm/C", Tolerance_%=0.5%, Value2=0.1W, Value_Code=1k00, ValueDisplayed=1.00k
R23: library part CMP-0023681-3, "RES, 11.8 k, 0.1%, 0.1 W, 0603", Manufacturer="Yageo America", Power_W=100mW, TempCo="25 ppm/C", Tolerance_%=0.1%, Value2=0.1W, Value_Code=11k8, ValueDisplayed=11.8k
U1: library part CMP-0123072-1, "Nanopower-IQ 200nA 200mA low-dropout (LDO) voltage regulator with fast transient response", Digikey Part Number=296-TPS7A0333DBVRCT-ND, Dropout Voltage=310mV, Manufacturer="Texas Instruments", Max Supply Voltage=6V, Min Supply Voltage=3.8V, Mouser Part Number=595-TPS7A0333DBVR, Nominal Supply Current=0.2uA, Operating Temperature Range="-40°C to +125°C", Output Voltage=3.3V
U2 U5: library part CMP-0093103-2, "Buck Converter, Adjustable, 4V-36V Input, 1-28V 1A Output, SOT23-6", Manufacturer="Texas Instruments", Max Supply Voltage=36V, Min Supply Voltage=4V, Nominal Supply Current=80uA, Operating Temperature Range="-40°C to +150°C", Output Voltage=1-28V, Switching Frequency=700kHz
U3: library part CMP-0127304-1, "Dual, 40-V, 1-MHz, low-power operational amplifier 8-SOT-23-THIN -40 to 125", Digikey Part Number=296-TLV9302IDDFRCT-ND, Input Bias Current=10pA, Input Offset Voltage=0.5mV, Manufacturer="Texas Instruments", Max Dual Supply Voltage=20V, Max Supply Voltage=40V, Min Dual Supply Voltage=2.25V, Min Supply Voltage=4.5V, Mouser Part Number=595-TLV9302IDDFR, Nominal Supply Current=150uA, Operating Temperature Range="-40°C to +125°C", Output Current Per Channel=60mA, Voltage Gain=130dB
U4: library part CMP-0096504-1, "50-V, universal 4-20-mA, ±20-mA current loop protector 8-SOT-23-THIN -40 to 125", Digikey Part Number=296-TPS26611DDFRCT-ND, Manufacturer="Texas Instruments", Max Supply Voltage=30V, Min Supply Voltage=2.25V, Mouser Part Number=595-TPS26611DDFR, Operating Temperature Range="-40°C to +125°C"
U6: library part CMP-0097359-1, "40-V, 1-MHz, RRO Operational Amplifiers for Cost-Sensitive Systems", Digikey Part Number=296-TLV9301IDCKRCT-ND, Input Bias Current=0.00001uA, Input Offset Voltage=0.5mV, Manufacturer="Texas Instruments", Max Dual Supply Voltage=20V, Max Supply Voltage=40V, Min Dual Supply Voltage=2.25V, Min Supply Voltage=4.5V, Mouser Part Number=595-TLV9301IDCKR, Nominal Supply Current=150uA, Operating Temperature Range="-40°C to +125°C", Output Current Per Channel=60mA, Voltage Gain=130dB
U7: library part CMP-0092737-1, "40-V, dual-channel, 4.5-MHz, rail-to-rail input/output, low-offset-voltage, low-noise op amp 8-VSSOP -40 to 125", Input Bias Current=0.00001uA, Input Offset Voltage=0.125mV, Manufacturer="Texas Instruments", Max Dual Supply Voltage=20V, Max Supply Voltage=40V, Min Dual Supply Voltage=1.35V, Min Supply Voltage=2.7V, Mouser Part Number=595-OPA2991IDGKR, Nominal Supply Current=560uA, Operating Temperature Range="-40°C to +125°C", Output Current Per Channel=75mA, Voltage Gain=145dB
U8: library part CMP-0124197-1, Manufacturer="Texas Instruments", Operating Temperature Range=to
U9 U14: library part CMP-0081715-3, "33 V Bidirectional Flat-Clamp Surge Protection Device, DRB0008A (VSON-8)", Alternate Manufacturer="Texas Instruments", Alternate PartNumber=TVS3301DRBT, Operating Temperature Range="-40 to 125 C", Rating=Catalog
U10: library part CMP-0123563-1, "1.65-V to 5.5-V 8-bit parallel-load shift register with voltage translation", Digikey Part Number=296-SN74LV8T165BQBRCT-ND, Frequency_Fixed=37.7MHz, Manufacturer="Texas Instruments", Max Supply Voltage=5.5V, Min Supply Voltage=1.65V, Mouser Part Number=595-SN74LV8T165BQBR, Nominal Supply Current=2uA, Operating Temperature Range="-40°C to +125°C"
U11: library part CMP-0051690-3, "Single Inverter, DRL0005A, LARGE T&R", Alternate Manufacturer="Texas Instruments", F @ Nom Voltage(Max)(Mhz)=150, Generic Part Number=SN74LVC1G04, ICC @ Nom Voltage(Max)(mA)=0.01, Operating Temperature Range(C)="-40 to 125,-40 to 85", Rating=Catalog, tpd @ Nom Voltage(Max)(ns)=7.5,5.2,4.2,3.7, Voltage(Nom)(V)=1.8,2.5,3.3,5
U12: library part CMP-0066783-1, "150-mA, 30-V, Ultra-Low IQ, Wide Input Low-Dropout Regulator with Reverse Current Protection, DBV0005A (SOT-23-5)", Alternate Manufacturer="Texas Instruments", Alternate PartNumber=TPS70950DBVT
ZZ1: library part CMP-0003616-3
ZZ2: library part CMP-0077236-1
ZZ3: library part CMP-0077237-1
ZZ4: library part CMP-0077238-1

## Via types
v1: diameter 50, hole 28, Top Layer to Bottom Layer, tented both sides, 48 vias
v2: diameter 19.68, hole 7.87, Top Layer to Bottom Layer, tented both sides, 13 vias

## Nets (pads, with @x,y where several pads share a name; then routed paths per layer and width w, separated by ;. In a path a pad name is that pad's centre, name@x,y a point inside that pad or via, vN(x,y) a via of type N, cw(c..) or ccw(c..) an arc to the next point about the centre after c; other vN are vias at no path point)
EF: J2.16 R14.1 U8.3 | length 1213.1
  Top Layer w10: R14.1@1011.86,545.67 1011.86,589.27 959.98,641.15 v1(959.98,649.51) 964.52,654.05 964.52,681.54 1022.35,739.37 U8.3@1109.67,739.37
  Bottom Layer w10: J2.16@257.48,315.35 700.58,315.35 959.98,574.75 v1(959.98,649.51)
